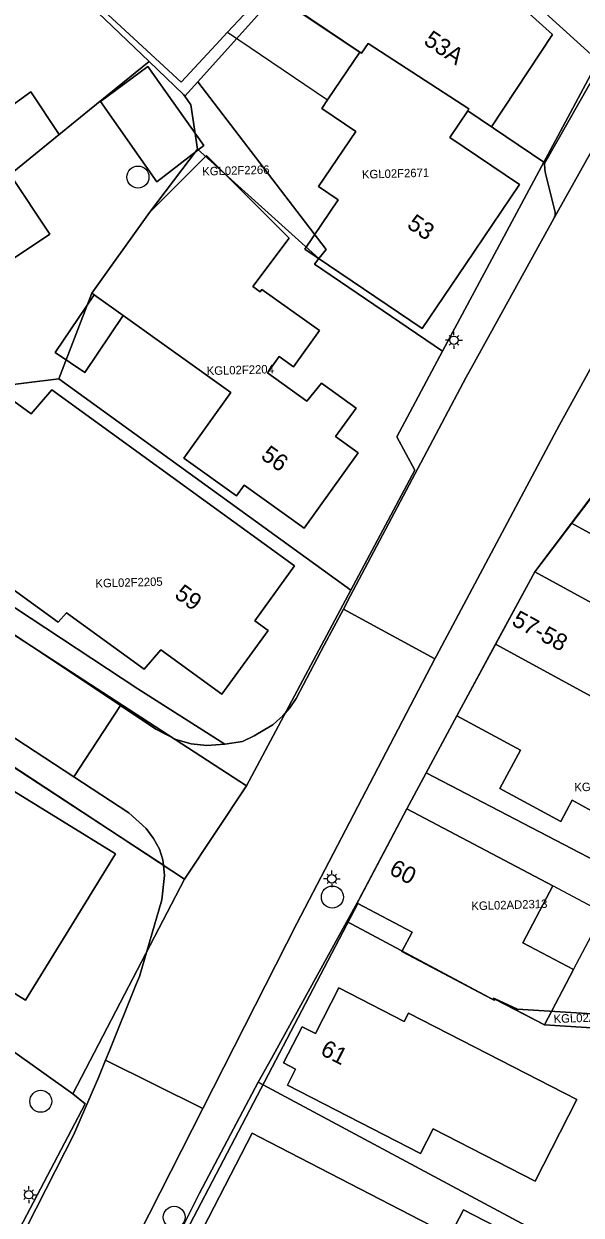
# Model space of a CAD drawing. Extents: x 124901 to 125496, y 515369 to 515789.
# Drawn here: x 125038.7 to 125071.7, y 515553.9 to 515624.4 of the extents above; entities that cross this region are included whole.
import ezdxf

# ---------------------------------------------------------------- set-up
doc = ezdxf.new("R2010")
doc.units = 0
for name, color, linetype in [('Gebouw', 7, 'Continuous'), ('Lichtmast', 7, 'Continuous'), ('Luifel', 7, 'Continuous'), ('Onbegroeid terrein', 7, 'Continuous'), ('Parkeren', 7, 'Continuous'), ('Perceelnummers', 7, 'Continuous'), ('Perceelsgrenzen', 7, 'Continuous'), ('Putten', 7, 'Continuous'), ('Teksten', 7, 'Continuous'), ('Voetpad', 7, 'Continuous'), ('Wegen drempel verkeerseiland', 7, 'Continuous'), ('Wegen lokale weg', 7, 'Continuous')]:
    doc.layers.add(name, color=color, linetype=linetype)

msp = doc.modelspace()

# ---------------------------------------------------------------- linework, layer by layer
at = {"layer": 'Gebouw'}
for points in [[(125058.033, 515632.121), (125057.086, 515632.984), (125054.984, 515630.678), (125050.63, 515625.902), (125051.713, 515624.895), (125052.837, 515626.56), (125058.582, 515622.681), (125058.681, 515622.614), (125059.078, 515623.201), (125065.039, 515619.326), (125064.966, 515619.218), (125066.376, 515618.266), (125069.982, 515623.717), (125060.408, 515632.366), (125059.619, 515631.522), (125058.465, 515632.595)], [(125050.63, 515625.902), (125043.969, 515631.974), (125040.949, 515628.785), (125040.275, 515628.074), (125040.883, 515627.512), (125048.014, 515620.914), (125050.076, 515623.133), (125050.752, 515623.86), (125051.713, 515624.895)], [(125062.278, 515606.343), (125064.837, 515610.133), (125068.026, 515614.856), (125063.901, 515617.641), (125064.966, 515619.218), (125065.039, 515619.326), (125059.078, 515623.201), (125058.681, 515622.614), (125058.582, 515622.681), (125056.677, 515619.859), (125056.335, 515619.353), (125058.347, 515617.994), (125056.146, 515614.734), (125057.308, 515613.95), (125055.337, 515611.03)], [(125049.357, 515617.16), (125046.049, 515621.837), (125043.251, 515619.764), (125046.583, 515615.022)], [(125040.799, 515617.816), (125039.117, 515620.346), (125033.445, 515616.247), (125031.891, 515617.5), (125022.867, 515611.5), (125026.487, 515606.055), (125037.474, 515613.36), (125036.716, 515614.502), (125037.892, 515615.456)], [(125055.3, 515594.54), (125058.495, 515599.009), (125057.152, 515599.969), (125058.363, 515601.645), (125056.312, 515603.115), (125055.452, 515602.054), (125053.119, 515603.722), (125053.813, 515604.692), (125054.658, 515604.087), (125056.194, 515606.235), (125052.797, 515608.663), (125052.695, 515608.519), (125052.255, 515608.834), (125054.412, 515611.683), (125049.516, 515616.581), (125046.139, 515613.205), (125042.736, 515608.443), (125042.875, 515608.343), (125044.587, 515607.12), (125050.96, 515602.565), (125048.182, 515598.68), (125051.29, 515596.459), (125051.738, 515597.086)], [(125030.033, 515600.721), (125036.675, 515605.137), (125034.644, 515608.192), (125040.245, 515611.916), (125037.892, 515615.456), (125036.716, 515614.502), (125037.474, 515613.36), (125026.487, 515606.055)], [(125044.587, 515607.12), (125042.875, 515608.343), (125040.566, 515604.923), (125042.309, 515603.746)], [(125052.366, 515589.074), (125054.717, 515592.314), (125040.36, 515602.731), (125039.139, 515601.311), (125036.94, 515602.907), (125031.626, 515596.727), (125036.431, 515593.241), (125035.834, 515592.546), (125040.742, 515588.985), (125041.224, 515589.545), (125045.823, 515586.209), (125046.813, 515587.359), (125050.429, 515584.736), (125053.158, 515588.499)], [(125074.327, 515581.59), (125076.802, 515580.247), (125080.423, 515586.916), (125082.767, 515585.713), (125084.07, 515588.113), (125080.052, 515590.255), (125079.301, 515589.076), (125073.913, 515592), (125072.762, 515589.88), (125068.935, 515591.958), (125064.321, 515583.46), (125068.082, 515581.418), (125066.86, 515579.167), (125070.468, 515577.208), (125071.151, 515578.466), (125072.294, 515577.845)], [(125031.151, 515583.287), (125027.217, 515576.897), (125024.827, 515578.368), (125022.298, 515574.26), (125028.478, 515570.459), (125029.923, 515572.807), (125032.429, 515571.264), (125032.123, 515570.767), (125038.802, 515566.655), (125041.518, 515571.067), (125044.124, 515575.3), (125037.863, 515579.155)], [(125061.362, 515577.957), (125058.422, 515572.385), (125058.472, 515572.359), (125061.677, 515570.668), (125061.07, 515569.518), (125065.991, 515566.921), (125066.447, 515566.681), (125066.494, 515566.769), (125069.501, 515565.182), (125071.228, 515568.455), (125068.221, 515570.041), (125069.994, 515573.402)], [(125057.34, 515567.378), (125055.956, 515564.678), (125055.175, 515565.078), (125054.076, 515562.933), (125054.785, 515562.57), (125054.304, 515561.631), (125062.183, 515557.592), (125062.928, 515559.044), (125066.681, 515557.12), (125068.959, 515555.952), (125071.431, 515560.775), (125064.627, 515564.261), (125061.459, 515565.884), (125061.208, 515565.395)], [(125052.661, 515558.549), (125052.21, 515558.782), (125046.412, 515547.549), (125071.932, 515534.376), (125078.519, 515547.138), (125064.721, 515554.261), (125063.932, 515552.731)]]:
    msp.add_lwpolyline(points, close=True, dxfattribs=at)
at = {"layer": 'Lichtmast'}
for p, q in [((125064.153, 515605.953), (125064.153, 515606.153)), ((125063.853, 515605.654), (125063.653, 515605.653)), ((125063.941, 515605.441), (125063.869, 515605.37)), ((125063.941, 515605.865), (125063.871, 515605.936)), ((125064.153, 515605.353), (125064.153, 515605.153)), ((125064.365, 515605.865), (125064.436, 515605.937)), ((125064.365, 515605.441), (125064.435, 515605.37)), ((125064.453, 515605.653), (125064.653, 515605.653)), ((125056.929, 515574.117), (125056.929, 515574.317)), ((125056.629, 515573.818), (125056.429, 515573.817)), ((125056.717, 515573.605), (125056.645, 515573.534)), ((125056.717, 515574.029), (125056.647, 515574.1)), ((125057.141, 515574.029), (125057.212, 515574.101)), ((125057.141, 515573.605), (125057.211, 515573.534)), ((125057.229, 515573.817), (125057.429, 515573.817)), ((125056.929, 515573.517), (125056.929, 515573.317)), ((125038.786, 515555.36), (125038.716, 515555.431)), ((125038.998, 515555.448), (125038.998, 515555.648)), ((125039.21, 515555.36), (125039.281, 515555.432)), ((125038.786, 515554.936), (125038.714, 515554.865)), ((125038.998, 515554.848), (125038.998, 515554.648)), ((125039.21, 515554.936), (125039.28, 515554.865)), ((125039.298, 515555.148), (125039.498, 515555.148))]:
    msp.add_line(p, q, dxfattribs=at)
for centre in [(125064.153, 515605.653), (125056.929, 515573.817), (125038.998, 515555.148)]:
    msp.add_circle(centre, 0.25, dxfattribs=at)
at = {"layer": 'Luifel'}
for points in [[(125056.677, 515619.859), (125058.582, 515622.681), (125052.837, 515626.56), (125051.713, 515624.895), (125050.752, 515623.86)], [(125073.001, 515571.815), (125069.994, 515573.402), (125068.221, 515570.041), (125071.228, 515568.455)]]:
    msp.add_lwpolyline(points, close=True, dxfattribs=at)
at = {"layer": 'Onbegroeid terrein'}
for points in [[(125060.408, 515632.366), (125069.982, 515623.717), (125066.376, 515618.266), (125064.966, 515619.218), (125063.901, 515617.641), (125068.026, 515614.856), (125064.837, 515610.133), (125062.278, 515606.343), (125055.337, 515611.03), (125057.308, 515613.95), (125056.146, 515614.734), (125058.347, 515617.994), (125056.335, 515619.353), (125056.677, 515619.859), (125058.582, 515622.681), (125052.837, 515626.56)], [(125035.4, 515546.426), (125041.156, 515557.703), (125041.651, 515558.673), (125043.145, 515562.119), (125043.544, 515563.105), (125043.748, 515563.61), (125045.321, 515567.498), (125045.546, 515568.055), (125046.874, 515572.577), (125047.038, 515574.017), (125046.969, 515574.62), (125038.47, 515580.19), (125024.631, 515589.269), (125024.258, 515589.652), (125023.849, 515590.085), (125011.59, 515610.348), (125000, 515629.377)], [(125051.713, 515624.895), (125050.752, 515623.86), (125050.076, 515623.133), (125048.014, 515620.914), (125040.883, 515627.512)], [(125030.959, 515594.579), (125045.442, 515585.041), (125050.596, 515581.784), (125051.634, 515581.935), (125052.335, 515582.28), (125052.967, 515582.644), (125053.443, 515582.927), (125053.67, 515583.13), (125054.038, 515583.459), (125054.449, 515583.92), (125054.817, 515584.486), (125056.479, 515587.624), (125057.609, 515589.753), (125058.023, 515590.533), (125062.379, 515598.744), (125064.885, 515603.466), (125065.259, 515604.145), (125070.056, 515612.85), (125070.135, 515613.049), (125070.15, 515613.216), (125070.086, 515613.465), (125069.565, 515615.51), (125069.537, 515615.75), (125069.519, 515616.097), (125072.2, 515620.809)], [(125072.515, 515596.65), (125068.935, 515591.958), (125072.762, 515589.88)], [(125072.294, 515577.845), (125071.151, 515578.466), (125070.468, 515577.208), (125066.86, 515579.167), (125068.082, 515581.418), (125064.321, 515583.46), (125061.362, 515577.957), (125069.994, 515573.402), (125068.221, 515570.041), (125071.228, 515568.455), (125069.501, 515565.182), (125066.494, 515566.769), (125066.447, 515566.681), (125065.991, 515566.921), (125061.07, 515569.518), (125061.677, 515570.668), (125058.472, 515572.359), (125045.678, 515547.925)]]:
    msp.add_lwpolyline(points, dxfattribs=at)
for points in [[(125046.049, 515621.837), (125049.357, 515617.16), (125046.583, 515615.022), (125043.251, 515619.764)], [(125036.675, 515605.137), (125030.033, 515600.721), (125026.487, 515606.055), (125022.867, 515611.5), (125031.891, 515617.5), (125033.445, 515616.247), (125039.117, 515620.346), (125040.799, 515617.816), (125037.892, 515615.456), (125040.245, 515611.916), (125034.644, 515608.192)], [(125058.495, 515599.009), (125055.3, 515594.54), (125051.738, 515597.086), (125051.29, 515596.459), (125048.182, 515598.68), (125050.96, 515602.565), (125044.587, 515607.12), (125042.309, 515603.746), (125040.566, 515604.923), (125042.875, 515608.343), (125042.736, 515608.443), (125046.139, 515613.205), (125049.516, 515616.581), (125054.412, 515611.683), (125052.255, 515608.834), (125052.695, 515608.519), (125052.797, 515608.663), (125056.194, 515606.235), (125054.658, 515604.087), (125053.813, 515604.692), (125053.119, 515603.722), (125055.452, 515602.054), (125056.312, 515603.115), (125058.363, 515601.645), (125057.152, 515599.969)], [(125054.717, 515592.314), (125052.366, 515589.074), (125053.158, 515588.499), (125050.429, 515584.736), (125046.813, 515587.359), (125045.823, 515586.209), (125041.224, 515589.545), (125040.742, 515588.985), (125035.834, 515592.546), (125036.431, 515593.241), (125031.626, 515596.727), (125036.94, 515602.907), (125039.139, 515601.311), (125040.36, 515602.731)], [(125027.217, 515576.897), (125031.151, 515583.287), (125037.863, 515579.155), (125044.124, 515575.3), (125041.518, 515571.067), (125038.802, 515566.655), (125032.123, 515570.767), (125032.429, 515571.264), (125029.923, 515572.807), (125028.478, 515570.459), (125022.298, 515574.26), (125024.827, 515578.368)], [(125055.956, 515564.678), (125057.34, 515567.378), (125061.208, 515565.395), (125061.459, 515565.884), (125064.627, 515564.261), (125071.431, 515560.775), (125068.959, 515555.952), (125066.681, 515557.12), (125062.928, 515559.044), (125062.183, 515557.592), (125054.304, 515561.631), (125054.785, 515562.57), (125054.076, 515562.933), (125055.175, 515565.078)], [(125052.21, 515558.782), (125052.661, 515558.549), (125063.932, 515552.731), (125064.721, 515554.261), (125078.519, 515547.138), (125071.932, 515534.376), (125046.412, 515547.549)]]:
    msp.add_lwpolyline(points, close=True, dxfattribs=at)
at = {"layer": 'Parkeren'}
msp.add_lwpolyline([(125070.056, 515612.85), (125074.966, 515621.628), (125077.049, 515625.289), (125081.443, 515633.011), (125089.462, 515645.498), (125089.281, 515645.41), (125086.621, 515644.747), (125086.531, 515644.661), (125086.43, 515644.565), (125079.729, 515634.043), (125075.311, 515626.278), (125073.228, 515622.617), (125072.2, 515620.809), (125069.519, 515616.097), (125069.537, 515615.75), (125069.565, 515615.51), (125070.086, 515613.465), (125070.15, 515613.216), (125070.135, 515613.049)], close=True, dxfattribs=at)
at = {"layer": 'Perceelsgrenzen'}
for points in [[(125040.931, 515627.093), (125037.137, 515630.723), (125036.712, 515631.413), (125031.866, 515639.28), (125034.423, 515641.126), (125026.885, 515653.376), (125023.812, 515658.371), (125019.579, 515665.251), (125016.351, 515670.496), (125013.58, 515690.889), (125023.847, 515691.023), (125024.009, 515686.713), (125031.069, 515680.399), (125080.294, 515636.377), (125072.681, 515622.173), (125060.212, 515633.452), (125055.522, 515628.217), (125053.571, 515626.038), (125048.992, 515620.927), (125048.229, 515620.075), (125048.15, 515620.185), (125046.127, 515622.121)], [(125072.681, 515622.173), (125069.998, 515617.166), (125069.468, 515616.178), (125064.966, 515619.218), (125065.039, 515619.326), (125059.078, 515623.201), (125058.681, 515622.614), (125058.582, 515622.681), (125053.571, 515626.038), (125055.522, 515628.217), (125060.212, 515633.452)], [(125037.343, 515613.557), (125036.019, 515612.482), (125024.2, 515604.829), (125020.38, 515611.076), (125035.076, 515623.364), (125040.931, 515627.093), (125046.127, 515622.121), (125042.594, 515619.273), (125036.716, 515614.502)], [(125056.156, 515610.477), (125056.589, 515611.016), (125048.992, 515620.927), (125053.571, 515626.038), (125058.582, 515622.681), (125058.681, 515622.614), (125059.078, 515623.201), (125065.039, 515619.326), (125064.966, 515619.218), (125069.468, 515616.178), (125063.483, 515605.009), (125055.912, 515610.161)], [(125037.343, 515613.557), (125036.716, 515614.502), (125042.594, 515619.273), (125046.127, 515622.121), (125048.15, 515620.185), (125048.229, 515620.075), (125048.595, 515619.565), (125048.974, 515616.948), (125046.139, 515613.205), (125042.736, 515608.443), (125040.778, 515603.38), (125036.94, 515602.907), (125031.626, 515596.727), (125030.112, 515595.131), (125024.2, 515604.829), (125036.019, 515612.482)], [(125048.229, 515620.075), (125048.992, 515620.927), (125056.589, 515611.016), (125056.156, 515610.477), (125048.974, 515616.948), (125048.595, 515619.565)], [(125063.483, 515605.009), (125060.771, 515599.949), (125061.843, 515597.969), (125058.053, 515590.876), (125040.778, 515603.38), (125042.736, 515608.443), (125046.139, 515613.205), (125048.974, 515616.948), (125056.156, 515610.477), (125055.912, 515610.161)], [(125087.836, 515585.679), (125086.845, 515583.619), (125082.657, 515585.769), (125083.865, 515587.883), (125071.114, 515594.848), (125072.151, 515596.222), (125072.515, 515596.65), (125075.821, 515602.821), (125075.449, 515603.021), (125076.944, 515605.812), (125077.359, 515605.589), (125080.84, 515612.087), (125097.499, 515603.161), (125098.736, 515599.084), (125091.393, 515585.313), (125088.493, 515586.859)], [(125051.878, 515579.322), (125031.826, 515592.319), (125030.112, 515595.131), (125031.626, 515596.727), (125036.94, 515602.907), (125040.778, 515603.38), (125058.053, 515590.876)], [(125083.966, 515578.671), (125077.827, 515582.053), (125075.257, 515583.391), (125075.107, 515583.064), (125066.616, 515587.688), (125068.935, 515591.958), (125071.114, 515594.848), (125083.865, 515587.883), (125082.657, 515585.769), (125086.845, 515583.619)], [(125079.786, 515570.89), (125078.613, 515571.606), (125073.03, 515574.6), (125062.507, 515580.086), (125064.321, 515583.46), (125066.616, 515587.688), (125075.107, 515583.064), (125075.257, 515583.391), (125077.827, 515582.053), (125083.966, 515578.671), (125080.656, 515572.359)], [(125048.213, 515573.798), (125041.613, 515561.12), (125028.478, 515570.459), (125027.6, 515570.999), (125022.54, 515574.061), (125021.181, 515574.949), (125030.952, 515585.122)], [(125066.579, 515566.705), (125066.535, 515566.655), (125057.813, 515571.288), (125058.521, 515572.573), (125061.362, 515577.957), (125062.507, 515580.086), (125073.03, 515574.6), (125078.613, 515571.606), (125079.786, 515570.89), (125082.519, 515569.594), (125082.349, 515569.052), (125082.085, 515568.592), (125081.214, 515567.072), (125081.016, 515566.727), (125081.04, 515566.715), (125079.962, 515564.502), (125079.408, 515564.541), (125074.312, 515566.651), (125073.909, 515565.739), (125067.903, 515566.122), (125066.588, 515566.716)], [(125021.181, 515574.949), (125022.54, 515574.061), (125027.6, 515570.999), (125028.478, 515570.459), (125041.613, 515561.12), (125042.332, 515560.528), (125035.799, 515548.142), (125007.677, 515565.251), (125018.012, 515571.65)], [(125052.576, 515561.797), (125053.357, 515563.193), (125057.813, 515571.288), (125066.535, 515566.655), (125066.579, 515566.705), (125069.501, 515565.182), (125075.403, 515564.824), (125079.408, 515564.541), (125082.662, 515563.194), (125083.621, 515565.449), (125085.722, 515564.404), (125087.207, 515563.666), (125088.685, 515562.931), (125090.172, 515562.192), (125091.65, 515561.458), (125093.201, 515560.687), (125094.12, 515560.23), (125111.126, 515551.777), (125110.925, 515551.284), (125104.374, 515534.324), (125104.265, 515534.108)], [(125069.501, 515565.182), (125066.579, 515566.705), (125066.588, 515566.716), (125067.903, 515566.122), (125073.909, 515565.739), (125074.312, 515566.651), (125079.408, 515564.541), (125075.403, 515564.824)], [(125104.265, 515534.108), (125099.167, 515524.054), (125098.866, 515523.485), (125088.766, 515528.652), (125088.185, 515527.527), (125074.377, 515534.655), (125072.184, 515534.116), (125071.932, 515534.376), (125046.412, 515547.549), (125045.511, 515548.07), (125049.098, 515555.247), (125052.576, 515561.797)]]:
    msp.add_lwpolyline(points, close=True, dxfattribs=at)
for points in [[(124998.603, 515662.333), (125000.264, 515652.44), (125001.498, 515645.089), (125001.763, 515642.97), (125002.972, 515639.501), (125011.19, 515626.123), (125015.832, 515618.523), (125020.38, 515611.076), (125024.2, 515604.829), (125030.112, 515595.131), (125031.826, 515592.319), (125051.878, 515579.322), (125048.213, 515573.798), (125030.952, 515585.122), (125024.631, 515589.269), (125023.849, 515590.085), (125023.679, 515590.367), (125014.335, 515605.811), (125003.919, 515622.943), (124994.885, 515637.794)], [(125002.221, 515491.957), (125012.299, 515514.356), (125013.576, 515513.702), (125016.718, 515511.968), (125028.241, 515533.814), (125035.799, 515548.142), (125042.332, 515560.528), (125041.613, 515561.12), (125048.213, 515573.798), (125051.878, 515579.322), (125058.053, 515590.876), (125061.843, 515597.969), (125060.771, 515599.949), (125063.483, 515605.009), (125069.468, 515616.178), (125069.998, 515617.166), (125072.681, 515622.173), (125080.294, 515636.377)], [(125072.151, 515596.222), (125071.114, 515594.848), (125068.935, 515591.958), (125066.616, 515587.688), (125064.321, 515583.46), (125062.507, 515580.086), (125061.362, 515577.957), (125058.521, 515572.573), (125057.813, 515571.288), (125053.357, 515563.193), (125052.576, 515561.797), (125049.098, 515555.247), (125045.511, 515548.07), (125045.434, 515547.916), (125040.275, 515537.401), (125039.722, 515536.273), (125039.253, 515535.311), (125026.224, 515508.579)]]:
    msp.add_lwpolyline(points, dxfattribs=at)
at = {"layer": 'Putten'}
for centre in [(125045.46, 515615.3), (125056.96, 515572.74), (125039.71, 515560.67), (125047.6, 515553.82)]:
    msp.add_circle(centre, 0.65, dxfattribs=at)
at = {"layer": 'Voetpad'}
for points in [[(125009.642, 515626.017), (125022.922, 515604.183), (125028.758, 515594.67), (125029.307, 515594.033), (125029.673, 515593.687), (125035.706, 515589.855), (125044.421, 515584.058), (125046.525, 515582.658), (125047.692, 515582.058), (125048.603, 515581.805), (125049.539, 515581.709), (125050.596, 515581.784), (125045.442, 515585.041), (125030.959, 515594.579), (125030.494, 515594.946), (125029.863, 515595.54), (125028.402, 515597.96), (125013.566, 515622.216), (125002.396, 515640.583)], [(125000, 515629.377), (125011.59, 515610.348), (125023.849, 515590.085), (125024.258, 515589.652), (125024.631, 515589.269), (125038.47, 515580.19), (125046.969, 515574.62), (125046.932, 515574.939), (125046.734, 515575.564), (125046.38, 515576.202), (125045.938, 515576.787), (125044.925, 515577.721), (125041.66, 515579.856), (125026.088, 515590.042), (125025.557, 515590.387), (125025.191, 515590.771), (125024.836, 515591.144), (125010.78, 515614.315), (125008.7, 515617.743), (125007.429, 515619.839), (125000, 515632.047)], [(125088.561, 515632.219), (125078.852, 515615.982), (125070.405, 515600.661), (125063.124, 515587.005), (125063.031, 515586.827), (125054.863, 515571.187), (125049.305, 515560.251), (125042.974, 515547.797), (125036.236, 515534.141), (125026.086, 515513.693), (125020.136, 515501.661)], [(125028.967, 515507.306), (125033.818, 515518.546), (125032.756, 515519.957), (125032.455, 515520.859), (125032.369, 515521.409), (125032.469, 515521.906), (125032.648, 515522.333), (125034.662, 515526.564), (125035.623, 515528.25), (125043.062, 515543.088), (125043.436, 515543.626), (125043.909, 515544.061), (125044.538, 515544.35), (125044.766, 515544.359), (125046.412, 515547.549), (125045.678, 515547.925), (125058.472, 515572.359), (125058.422, 515572.385), (125061.362, 515577.957), (125064.321, 515583.46), (125068.935, 515591.958), (125072.515, 515596.65)]]:
    msp.add_lwpolyline(points, dxfattribs=at)
at = {"layer": 'Wegen drempel verkeerseiland'}
msp.add_lwpolyline([(125046.969, 515574.62), (125047.038, 515574.017), (125046.874, 515572.577), (125045.546, 515568.055), (125045.321, 515567.498), (125043.748, 515563.61), (125043.544, 515563.105), (125049.305, 515560.251), (125054.863, 515571.187), (125063.031, 515586.827), (125057.609, 515589.753), (125056.479, 515587.624), (125054.817, 515584.486), (125054.449, 515583.92), (125054.038, 515583.459), (125053.67, 515583.13), (125053.443, 515582.927), (125052.967, 515582.644), (125052.335, 515582.28), (125051.634, 515581.935), (125050.596, 515581.784), (125049.539, 515581.709), (125048.603, 515581.805), (125047.692, 515582.058), (125046.525, 515582.658), (125044.421, 515584.058), (125041.66, 515579.856), (125044.925, 515577.721), (125045.938, 515576.787), (125046.38, 515576.202), (125046.734, 515575.564), (125046.932, 515574.939)], close=True, dxfattribs=at)
at = {"layer": 'Wegen lokale weg'}
for points in [[(125063.124, 515587.005), (125070.405, 515600.661), (125078.852, 515615.982), (125088.561, 515632.219), (125092.011, 515637.687), (125096.857, 515644.957), (125091.656, 515648.529), (125089.696, 515645.675), (125089.591, 515645.587), (125089.462, 515645.498), (125081.443, 515633.011), (125077.049, 515625.289), (125074.966, 515621.628), (125070.056, 515612.85), (125065.259, 515604.145), (125064.885, 515603.466), (125062.379, 515598.744), (125058.023, 515590.533), (125057.609, 515589.753), (125063.031, 515586.827)], [(125026.086, 515513.693), (125036.236, 515534.141), (125042.974, 515547.797), (125049.305, 515560.251), (125043.544, 515563.105), (125043.145, 515562.119), (125041.651, 515558.673), (125041.156, 515557.703), (125035.4, 515546.426), (125024.23, 515523.143), (125019.645, 515514.193), (125018.594, 515512.141), (125018.029, 515511.051), (125014.086, 515503.449), (125012.423, 515500), (125010.577, 515496.172), (125008.397, 515491.076), (125013.788, 515489.05), (125018.302, 515500), (125018.695, 515500.954), (125020.136, 515501.661)]]:
    msp.add_lwpolyline(points, close=True, dxfattribs=at)
msp.add_lwpolyline([(125012.396, 515615.297), (125010.78, 515614.315), (125024.836, 515591.144), (125025.191, 515590.771), (125025.557, 515590.387), (125026.088, 515590.042), (125041.66, 515579.856), (125044.421, 515584.058), (125035.706, 515589.855), (125029.673, 515593.687), (125029.307, 515594.033)], dxfattribs=at)

# ---------------------------------------------------------------- texts
at = {"layer": 'Perceelnummers'}
for s, rotation, p in [('KGL02F2266', 1.63043, (125049.268, 515615.383)), ('KGL02F2671', 1.63054, (125058.717, 515615.205)), ('KGL02F2204', 1.63044, (125049.531, 515603.593)), ('KGL02F2205', 1.63036, (125042.95, 515591.032)), ('KGL02AD23', 1.43253, (125071.28, 515578.985)), ('KGL02AD2313', 1.8288, (125065.191, 515571.959)), ('KGL02AD2310', 1.82886, (125070.056, 515565.294))]:
    msp.add_text(s, height=0.5, rotation=rotation, dxfattribs=at).set_placement(p)
at = {"layer": 'Teksten'}
for s, rotation, p in [('53A', 326.5, (125062.305, 515623.194)), ('53', 326, (125061.316, 515612.347)), ('56', 324.4, (125052.668, 515598.696)), ('59', 324, (125047.559, 515590.492)), ('57-58', 331.5, (125067.51, 515588.856)), ('60', 332.2, (125060.255, 515574.137)), ('61', 332.9, (125056.188, 515563.457))]:
    msp.add_text(s, height=1, rotation=rotation, dxfattribs=at).set_placement(p)

doc.saveas('drawing.dxf')
